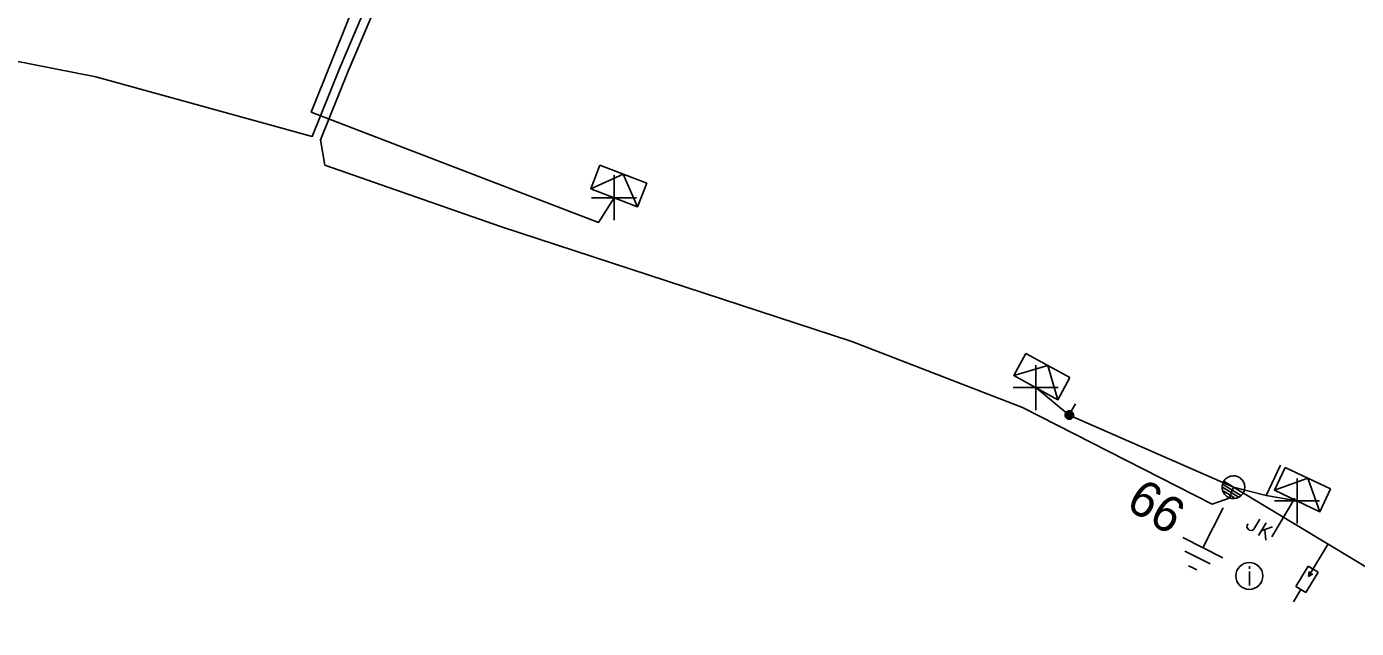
# Model space of a CAD drawing. Extents: x -540247 to -537390, y -1183887 to -1180355.
# Drawn here: x -537727.87 to -537690.84, y -1180542.13 to -1180525.39 of the extents above; entities that cross this region are included whole.
import ezdxf

# ---------------------------------------------------------------- set-up
doc = ezdxf.new("R2010")
doc.units = 0
for name, color, linetype in [('Vrstva 1', 7, 'Continuous'), ('Vrstva 10', 7, 'Continuous'), ('Vrstva 13', 7, 'Continuous'), ('Vrstva 14', 7, 'Continuous'), ('Vrstva 15', 7, 'Continuous'), ('Vrstva 16', 7, 'Continuous'), ('Vrstva 18', 7, 'Continuous'), ('Vrstva 2', 7, 'Continuous'), ('Vrstva 31', 7, 'Continuous'), ('Vrstva 34', 7, 'Continuous'), ('Vrstva 36', 7, 'Continuous'), ('Vrstva 5', 7, 'Continuous'), ('Vrstva 50', 7, 'Continuous'), ('Vrstva 52', 7, 'Continuous'), ('Vrstva 54', 7, 'Continuous'), ('Vrstva 8', 7, 'Continuous'), ('Vrstva 9', 7, 'Continuous')]:
    doc.layers.add(name, color=color, linetype=linetype)

# ---------------------------------------------------------------- blocks, each defined once
blk = doc.blocks.new('NN440')
at = {"layer": 'Vrstva 2'}
for points in [[(0.631, -0.004), (0.627, 0.062), (0.617, 0.127), (0.6, 0.191), (0.577, 0.252), (0.547, 0.311), (0.511, 0.366), (0.469, 0.417), (0.423, 0.464), (0.371, 0.505), (0.316, 0.542), (0.257, 0.571), (0.196, 0.595), (0.132, 0.612), (0.067, 0.622), (0.001, 0.626), (-0.065, 0.622), (-0.13, 0.612), (-0.194, 0.595), (-0.255, 0.571), (-0.314, 0.542), (-0.369, 0.505), (-0.42, 0.464), (-0.467, 0.417), (-0.509, 0.366), (-0.544, 0.311), (-0.574, 0.252), (-0.598, 0.191), (-0.615, 0.127), (-0.626, 0.062), (-0.629, -0.004), (-0.626, -0.07), (-0.615, -0.135), (-0.598, -0.199), (-0.574, -0.26), (-0.544, -0.319), (-0.509, -0.374), (-0.467, -0.426), (-0.42, -0.472), (-0.369, -0.514), (-0.314, -0.55), (-0.255, -0.58), (-0.194, -0.603), (-0.13, -0.62), (-0.065, -0.631), (0.001, -0.634), (0.067, -0.631), (0.132, -0.62), (0.196, -0.603), (0.257, -0.58), (0.316, -0.55), (0.371, -0.514), (0.423, -0.472), (0.469, -0.426), (0.511, -0.374), (0.547, -0.319), (0.577, -0.26), (0.6, -0.199), (0.617, -0.135), (0.627, -0.07), (0.631, -0.004)], [(-0.631, 0), (0.629, 0)], [(-0.601, -0.177), (0.57, -0.177)], [(-0.513, -0.325), (0.501, -0.325)], [(-0.375, -0.473), (0.353, -0.473)]]:
    blk.add_lwpolyline(points, dxfattribs=at)
blk = doc.blocks.new('NN840')
at = {"layer": 'Vrstva 15'}
for points in [[(0.003, 0.619), (0.003, -0.631)], [(-0.745, -0.71), (-0.745, -0.66)], [(-0.73, -0.764), (-0.745, -0.71)], [(-0.538, -0.71), (-0.558, -0.764)], [(-0.538, -0.385), (-0.538, -0.71)], [(-0.332, -0.385), (-0.332, -0.798)], [(-0.332, -0.641), (-0.125, -0.385)], [(-0.263, -0.557), (-0.091, -0.798)], [(-0.657, -0.798), (-0.73, -0.764)], [(-0.627, -0.798), (-0.657, -0.798)], [(-0.558, -0.764), (-0.627, -0.798)]]:
    blk.add_lwpolyline(points, dxfattribs=at)
blk = doc.blocks.new('NN770')
at = {"layer": 'Vrstva 10'}
for p, q in [((0.002, 0.187), (0.002, 0.263)), ((0.002, -0.276), (0.002, 0.111))]:
    blk.add_line(p, q, dxfattribs=at)
blk.add_circle((0, -0.008), 0.375, dxfattribs=at)
blk = doc.blocks.new('NN800')
at = {"layer": 'Vrstva 1'}
for points in [[(-0.442, 0.442), (0.442, -0.442)], [(-0.442, -0.442), (0.442, 0.442)]]:
    blk.add_lwpolyline(points, dxfattribs=at)
blk = doc.blocks.new('NN820')
at = {"layer": 'Vrstva 13'}
for points in [[(-0.003, 0.004), (-0.003, -1.049)], [(-0.165, -0.813), (0.165, -0.813)], [(-0.165, -1.473), (-0.165, -0.813)], [(-0.003, -1.049), (-0.062, -0.926)], [(-0.003, -1.049), (0.057, -0.926)], [(0.165, -0.813), (0.165, -1.473)], [(0.165, -1.473), (-0.165, -1.473)], [(-0.003, -1.473), (-0.003, -1.871)]]:
    blk.add_lwpolyline(points, dxfattribs=at)
blk = doc.blocks.new('NN630')
at = {"layer": 'Vrstva 9'}
for points in [[(-0.003, -0.7), (-0.703, 0)], [(-0.703, -0.7), (-0.703, 0), (0.697, 0), (0.697, -0.7)], [(-0.003, -0.7), (0.697, 0)], [(-0.703, -0.7), (0.697, -0.7)]]:
    blk.add_lwpolyline(points, dxfattribs=at)
blk = doc.blocks.new('NN810')
at = {"layer": 'Vrstva 14'}
for points in [[(0.004, -0.64), (0.004, -1.89)], [(0.629, -1.89), (-0.621, -1.89)], [(0.388, -2.2), (-0.399, -2.2)], [(0.004, -2.515), (-0.124, -2.515)], [(0.137, -2.515), (0.004, -2.515)]]:
    blk.add_lwpolyline(points, dxfattribs=at)
blk = doc.blocks.new('NN500')
at = {"layer": 'Vrstva 2'}
for points in [[(-0.001, -0.235), (0.023, -0.234), (0.048, -0.23), (0.071, -0.224), (0.094, -0.215), (0.116, -0.204), (0.137, -0.191), (0.156, -0.175), (0.173, -0.158), (0.189, -0.139), (0.202, -0.118), (0.213, -0.096), (0.222, -0.073), (0.229, -0.049), (0.232, -0.025), (0.234, 0), (0.232, 0.024), (0.229, 0.048), (0.222, 0.072), (0.213, 0.095), (0.202, 0.117), (0.189, 0.138), (0.173, 0.157), (0.156, 0.174), (0.137, 0.19), (0.116, 0.203), (0.094, 0.214), (0.071, 0.223), (0.048, 0.229), (0.023, 0.233), (-0.001, 0.235), (-0.026, 0.233), (-0.05, 0.229), (-0.074, 0.223), (-0.097, 0.214), (-0.119, 0.203), (-0.139, 0.19), (-0.158, 0.174), (-0.176, 0.157), (-0.191, 0.138), (-0.205, 0.117), (-0.216, 0.095), (-0.225, 0.072), (-0.231, 0.048), (-0.235, 0.024), (-0.236, 0), (-0.235, -0.025), (-0.231, -0.049), (-0.225, -0.073), (-0.216, -0.096), (-0.205, -0.118), (-0.191, -0.139), (-0.176, -0.158), (-0.158, -0.175), (-0.139, -0.191), (-0.119, -0.204), (-0.097, -0.215), (-0.074, -0.224), (-0.05, -0.23), (-0.026, -0.234), (-0.001, -0.235)], [(-0.001, -0.235), (0.023, -0.234), (0.048, -0.23), (0.071, -0.224), (0.094, -0.215), (0.116, -0.204), (0.137, -0.191), (0.156, -0.175), (0.173, -0.158), (0.189, -0.139), (0.202, -0.118), (0.213, -0.096), (0.222, -0.073), (0.229, -0.049), (0.232, -0.025), (0.234, 0), (0.232, 0.024), (0.229, 0.048), (0.222, 0.072), (0.213, 0.095), (0.202, 0.117), (0.189, 0.138), (0.173, 0.157), (0.156, 0.174), (0.137, 0.19), (0.116, 0.203), (0.094, 0.214), (0.071, 0.223), (0.048, 0.229), (0.023, 0.233), (-0.001, 0.235), (-0.026, 0.233), (-0.05, 0.229), (-0.074, 0.223), (-0.097, 0.214), (-0.119, 0.203), (-0.139, 0.19), (-0.158, 0.174), (-0.176, 0.157), (-0.191, 0.138), (-0.205, 0.117), (-0.216, 0.095), (-0.225, 0.072), (-0.231, 0.048), (-0.235, 0.024), (-0.236, 0), (-0.235, -0.025), (-0.231, -0.049), (-0.225, -0.073), (-0.216, -0.096), (-0.205, -0.118), (-0.191, -0.139), (-0.176, -0.158), (-0.158, -0.175), (-0.139, -0.191), (-0.119, -0.204), (-0.097, -0.215), (-0.074, -0.224), (-0.05, -0.23), (-0.026, -0.234), (-0.001, -0.235)], [(-0.001, -0.206), (0.02, -0.205), (0.041, -0.201), (0.062, -0.196), (0.082, -0.188), (0.101, -0.178), (0.12, -0.167), (0.136, -0.153), (0.151, -0.138), (0.165, -0.121), (0.177, -0.103), (0.186, -0.084), (0.194, -0.064), (0.2, -0.043), (0.203, -0.022), (0.204, 0), (0.203, 0.021), (0.2, 0.042), (0.194, 0.063), (0.186, 0.083), (0.177, 0.102), (0.165, 0.12), (0.151, 0.137), (0.136, 0.152), (0.12, 0.166), (0.101, 0.177), (0.082, 0.187), (0.062, 0.195), (0.041, 0.2), (0.02, 0.204), (-0.001, 0.205), (-0.023, 0.204), (-0.044, 0.2), (-0.065, 0.195), (-0.085, 0.187), (-0.104, 0.177), (-0.122, 0.166), (-0.139, 0.152), (-0.154, 0.137), (-0.167, 0.12), (-0.179, 0.102), (-0.189, 0.083), (-0.197, 0.063), (-0.202, 0.042), (-0.205, 0.021), (-0.207, 0), (-0.205, -0.022), (-0.202, -0.043), (-0.197, -0.064), (-0.189, -0.084), (-0.179, -0.103), (-0.167, -0.121), (-0.154, -0.138), (-0.139, -0.153), (-0.122, -0.167), (-0.104, -0.178), (-0.085, -0.188), (-0.065, -0.196), (-0.044, -0.201), (-0.023, -0.205), (-0.001, -0.206)], [(-0.001, -0.176), (0.017, -0.175), (0.035, -0.172), (0.053, -0.168), (0.07, -0.161), (0.087, -0.153), (0.102, -0.143), (0.116, -0.131), (0.129, -0.118), (0.141, -0.104), (0.151, -0.088), (0.159, -0.072), (0.166, -0.055), (0.171, -0.037), (0.174, -0.019), (0.175, 0), (0.174, 0.018), (0.171, 0.036), (0.166, 0.054), (0.159, 0.071), (0.151, 0.087), (0.141, 0.103), (0.129, 0.117), (0.116, 0.13), (0.102, 0.142), (0.087, 0.152), (0.07, 0.16), (0.053, 0.167), (0.035, 0.172), (0.017, 0.174), (-0.001, 0.175), (-0.02, 0.174), (-0.038, 0.172), (-0.056, 0.167), (-0.073, 0.16), (-0.089, 0.152), (-0.105, 0.142), (-0.119, 0.13), (-0.132, 0.117), (-0.143, 0.103), (-0.153, 0.087), (-0.162, 0.071), (-0.168, 0.054), (-0.173, 0.036), (-0.176, 0.018), (-0.177, 0), (-0.176, -0.019), (-0.173, -0.037), (-0.168, -0.055), (-0.162, -0.072), (-0.153, -0.088), (-0.143, -0.104), (-0.132, -0.118), (-0.119, -0.131), (-0.105, -0.143), (-0.089, -0.153), (-0.073, -0.161), (-0.056, -0.168), (-0.038, -0.172), (-0.02, -0.175), (-0.001, -0.176)], [(-0.001, -0.147), (0.014, -0.146), (0.029, -0.143), (0.044, -0.139), (0.058, -0.134), (0.072, -0.127), (0.085, -0.119), (0.097, -0.109), (0.107, -0.098), (0.117, -0.086), (0.125, -0.073), (0.132, -0.06), (0.138, -0.046), (0.142, -0.031), (0.144, -0.016), (0.145, 0), (0.144, 0.015), (0.142, 0.03), (0.138, 0.045), (0.132, 0.059), (0.125, 0.073), (0.117, 0.086), (0.107, 0.097), (0.097, 0.108), (0.085, 0.118), (0.072, 0.126), (0.058, 0.133), (0.044, 0.139), (0.029, 0.143), (0.014, 0.145), (-0.001, 0.146), (-0.017, 0.145), (-0.032, 0.143), (-0.046, 0.139), (-0.061, 0.133), (-0.074, 0.126), (-0.087, 0.118), (-0.099, 0.108), (-0.11, 0.097), (-0.119, 0.086), (-0.128, 0.073), (-0.135, 0.059), (-0.14, 0.045), (-0.144, 0.03), (-0.147, 0.015), (-0.147, 0), (-0.147, -0.016), (-0.144, -0.031), (-0.14, -0.046), (-0.135, -0.06), (-0.128, -0.073), (-0.119, -0.086), (-0.11, -0.098), (-0.099, -0.109), (-0.087, -0.119), (-0.074, -0.127), (-0.061, -0.134), (-0.046, -0.139), (-0.032, -0.143), (-0.017, -0.146), (-0.001, -0.147)], [(-0.001, -0.117), (0.011, -0.116), (0.023, -0.114), (0.035, -0.111), (0.046, -0.107), (0.057, -0.101), (0.067, -0.095), (0.077, -0.087), (0.085, -0.078), (0.093, -0.069), (0.1, -0.059), (0.105, -0.048), (0.11, -0.036), (0.113, -0.025), (0.115, -0.013), (0.115, 0), (0.115, 0.012), (0.113, 0.024), (0.11, 0.036), (0.105, 0.047), (0.1, 0.058), (0.093, 0.068), (0.085, 0.078), (0.077, 0.086), (0.067, 0.094), (0.057, 0.101), (0.046, 0.106), (0.035, 0.11), (0.023, 0.114), (0.011, 0.116), (-0.001, 0.116), (-0.013, 0.116), (-0.025, 0.114), (-0.037, 0.11), (-0.049, 0.106), (-0.059, 0.101), (-0.07, 0.094), (-0.079, 0.086), (-0.088, 0.078), (-0.096, 0.068), (-0.102, 0.058), (-0.108, 0.047), (-0.112, 0.036), (-0.115, 0.024), (-0.117, 0.012), (-0.118, 0), (-0.117, -0.013), (-0.115, -0.025), (-0.112, -0.036), (-0.108, -0.048), (-0.102, -0.059), (-0.096, -0.069), (-0.088, -0.078), (-0.079, -0.087), (-0.07, -0.095), (-0.059, -0.101), (-0.049, -0.107), (-0.037, -0.111), (-0.025, -0.114), (-0.013, -0.116), (-0.001, -0.117)], [(-0.001, -0.087), (0.008, -0.087), (0.017, -0.085), (0.026, -0.083), (0.034, -0.08), (0.042, -0.076), (0.05, -0.071), (0.057, -0.065), (0.063, -0.059), (0.069, -0.051), (0.074, -0.044), (0.078, -0.036), (0.081, -0.027), (0.084, -0.019), (0.085, -0.01), (0.086, 0), (0.085, 0.009), (0.084, 0.018), (0.081, 0.026), (0.078, 0.035), (0.074, 0.043), (0.069, 0.051), (0.063, 0.058), (0.057, 0.064), (0.05, 0.07), (0.042, 0.075), (0.034, 0.079), (0.026, 0.082), (0.017, 0.085), (0.008, 0.086), (-0.001, 0.087), (-0.01, 0.086), (-0.019, 0.085), (-0.028, 0.082), (-0.037, 0.079), (-0.045, 0.075), (-0.052, 0.07), (-0.059, 0.064), (-0.066, 0.058), (-0.072, 0.051), (-0.077, 0.043), (-0.081, 0.035), (-0.084, 0.026), (-0.086, 0.018), (-0.088, 0.009), (-0.088, 0), (-0.088, -0.01), (-0.086, -0.019), (-0.084, -0.027), (-0.081, -0.036), (-0.077, -0.044), (-0.072, -0.052), (-0.066, -0.059), (-0.059, -0.065), (-0.052, -0.071), (-0.045, -0.076), (-0.037, -0.08), (-0.028, -0.083), (-0.019, -0.085), (-0.01, -0.087), (-0.001, -0.087)], [(-0.001, -0.058), (0.005, -0.057), (0.011, -0.056), (0.016, -0.055), (0.022, -0.053), (0.027, -0.05), (0.032, -0.047), (0.037, -0.043), (0.041, -0.039), (0.045, -0.034), (0.048, -0.029), (0.051, -0.024), (0.053, -0.018), (0.055, -0.012), (0.056, -0.006), (0.056, 0), (0.056, 0.006), (0.055, 0.011), (0.053, 0.017), (0.051, 0.023), (0.048, 0.028), (0.045, 0.033), (0.041, 0.038), (0.037, 0.042), (0.032, 0.046), (0.027, 0.049), (0.022, 0.052), (0.016, 0.054), (0.011, 0.056), (0.005, 0.057), (-0.001, 0.057), (-0.007, 0.057), (-0.013, 0.056), (-0.019, 0.054), (-0.025, 0.052), (-0.03, 0.049), (-0.035, 0.046), (-0.04, 0.042), (-0.044, 0.038), (-0.048, 0.033), (-0.051, 0.028), (-0.054, 0.023), (-0.056, 0.017), (-0.057, 0.011), (-0.058, 0.006), (-0.059, 0), (-0.058, -0.006), (-0.057, -0.012), (-0.056, -0.018), (-0.054, -0.024), (-0.051, -0.029), (-0.048, -0.034), (-0.044, -0.039), (-0.04, -0.043), (-0.035, -0.047), (-0.03, -0.05), (-0.025, -0.053), (-0.019, -0.055), (-0.013, -0.056), (-0.007, -0.057), (-0.001, -0.058)], [(-0.001, -0.028), (0.002, -0.028), (0.005, -0.028), (0.007, -0.027), (0.01, -0.026), (0.013, -0.024), (0.015, -0.023), (0.017, -0.021), (0.019, -0.019), (0.021, -0.017), (0.023, -0.014), (0.024, -0.012), (0.025, -0.009), (0.026, -0.006), (0.026, -0.003), (0.027, 0), (0.026, 0.002), (0.026, 0.005), (0.025, 0.008), (0.024, 0.011), (0.023, 0.013), (0.021, 0.016), (0.019, 0.018), (0.017, 0.02), (0.015, 0.022), (0.013, 0.024), (0.01, 0.025), (0.007, 0.026), (0.005, 0.027), (0.002, 0.027), (-0.001, 0.027), (-0.004, 0.027), (-0.007, 0.027), (-0.01, 0.026), (-0.012, 0.025), (-0.015, 0.024), (-0.018, 0.022), (-0.02, 0.02), (-0.022, 0.018), (-0.024, 0.016), (-0.025, 0.013), (-0.027, 0.011), (-0.028, 0.008), (-0.028, 0.005), (-0.029, 0.002), (-0.029, 0), (-0.029, -0.003), (-0.028, -0.006), (-0.028, -0.009), (-0.027, -0.012), (-0.025, -0.014), (-0.024, -0.017), (-0.022, -0.019), (-0.02, -0.021), (-0.018, -0.023), (-0.015, -0.024), (-0.012, -0.026), (-0.01, -0.027), (-0.007, -0.028), (-0.004, -0.028), (-0.001, -0.028)], [(0.234, 0), (0.704, 0)]]:
    blk.add_lwpolyline(points, dxfattribs=at)
blk = doc.blocks.new('NN510')
at = {"layer": 'Vrstva 2'}
blk.add_lwpolyline([(0.001, 0.002), (0.001, 0.939)], dxfattribs=at)

msp = doc.modelspace()

# ---------------------------------------------------------------- linework, layer by layer
at = {"layer": 'Vrstva 5'}
for points in [[(-537734.68, -1180524.19), (-537734.74, -1180524.45), (-537732.42, -1180525.38), (-537728.3, -1180526.32), (-537725.94, -1180526.78), (-537719.916, -1180528.443), (-537719.145, -1180526.532), (-537715.575, -1180518.142), (-537712.055, -1180509.59), (-537710.072, -1180505.214), (-537708.029, -1180501.425), (-537707.177, -1180501.531), (-537706.489, -1180502.117), (-537706.751, -1180502.897)], [(-537694.259, -1180538.2), (-537694.383, -1180538.509), (-537694.85, -1180538.67), (-537700.14, -1180535.98), (-537704.89, -1180534.15), (-537714.67, -1180530.95), (-537719.56, -1180529.24), (-537719.684, -1180528.537), (-537718.915, -1180526.628), (-537715.345, -1180518.238), (-537711.825, -1180509.69), (-537709.848, -1180505.326), (-537707.891, -1180501.695), (-537707.283, -1180501.769), (-537706.751, -1180502.223), (-537706.972, -1180502.847)]]:
    msp.add_lwpolyline(points, dxfattribs=at)
at = {"layer": 'Vrstva 50'}
msp.add_lwpolyline([(-537694.26, -1180538.199), (-537691.624, -1180539.786), (-537675.507, -1180549.486), (-537663.756, -1180552.682), (-537651.753, -1180559.088), (-537616.15, -1180576.16), (-537591.135, -1180593.384), (-537584.357, -1180598.332)], dxfattribs=at)
at = {"layer": 'Vrstva 52'}
msp.add_lwpolyline([(-537706.972, -1180502.847), (-537709.876, -1180502.687), (-537719.944, -1180527.767), (-537711.939, -1180530.834), (-537711.509, -1180530.148)], dxfattribs=at)
at = {"layer": 'Vrstva 54'}
msp.add_lwpolyline([(-537694.26, -1180538.2), (-537693.348, -1180538.435), (-537692.489, -1180538.584)], dxfattribs=at)
at = {"layer": 'Vrstva 8'}
msp.add_lwpolyline([(-537694.26, -1180538.2), (-537698.832, -1180536.193), (-537699.768, -1180535.429)], dxfattribs=at)

# ---------------------------------------------------------------- block references
at = {"layer": 'Vrstva 13', "xscale": 0.5, "yscale": 0.5}
for name, p, rotation in [('NN500', (-537698.832, -1180536.193), 61.31899999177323), ('NN440', (-537694.26, -1180538.199), -32.04825282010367)]:
    msp.add_blockref(name, p, dxfattribs=dict(at, rotation=rotation))
at = {"layer": 'Vrstva 13', "rotation": -25.18302502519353}
msp.add_blockref('NN510', (-537693.349, -1180538.436), dxfattribs=at)
at = {"layer": 'Vrstva 15', "rotation": -26.91949160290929}
msp.add_blockref('NN810', (-537694.261, -1180538.2), dxfattribs=at)
at = {"layer": 'Vrstva 16', "rotation": -31.042769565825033}
msp.add_blockref('NN820', (-537691.624, -1180539.786), dxfattribs=at)
at = {"layer": 'Vrstva 18', "rotation": -31.049908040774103}
msp.add_blockref('NN840', (-537692.87, -1180539.036), dxfattribs=at)
at = {"layer": 'Vrstva 31'}
for p, rotation in [((-537711.509, -1180530.148), 158.978883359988), ((-537699.768, -1180535.429), 151.31901392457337), ((-537692.489, -1180538.584), 154.81697500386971)]:
    msp.add_blockref('NN630', p, dxfattribs=dict(at, rotation=rotation))
at = {"layer": 'Vrstva 34'}
for p, rotation in [((-537711.509, -1180530.148), 45), ((-537699.768, -1180535.429), 45), ((-537692.489, -1180538.584), 44.99999995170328)]:
    msp.add_blockref('NN800', p, dxfattribs=dict(at, rotation=rotation))
at = {"layer": 'Vrstva 36'}
msp.add_blockref('NN770', (-537693.82, -1180540.662), dxfattribs=at)

# ---------------------------------------------------------------- texts
at = {"layer": 'Vrstva 14'}
msp.add_text('66', height=1, rotation=327.884, dxfattribs=at).set_placement((-537697.298, -1180538.761))

doc.saveas('drawing.dxf')
